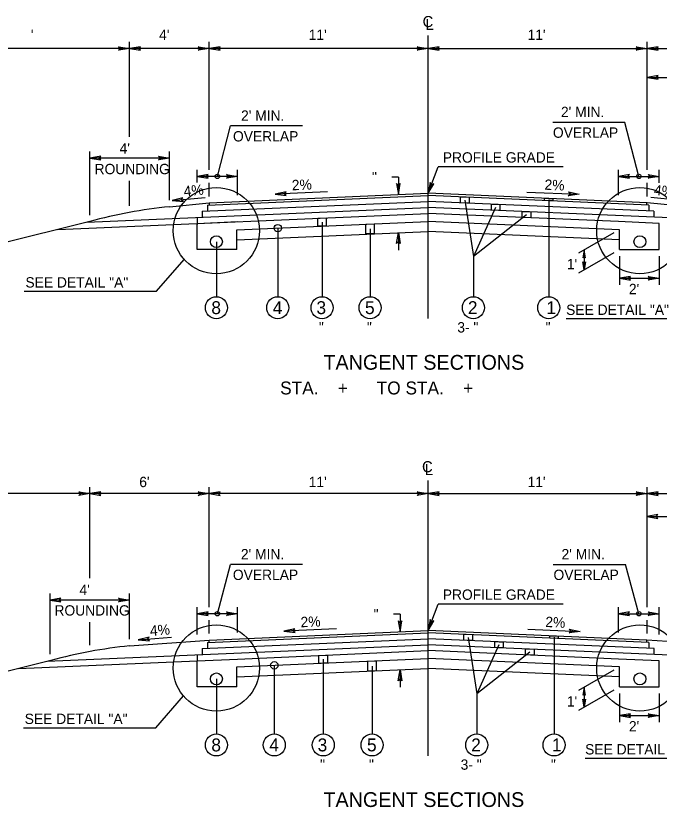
# Model space of a CAD drawing. Extents: x -540 to 1231, y -564 to 421.
# Drawn here: x -54.4 to 32.7, y 179.1 to 286.3 of the extents above; entities that cross this region are included whole.
import ezdxf

# ---------------------------------------------------------------- set-up
doc = ezdxf.new("R2010")
doc.units = 0
doc.layers.add('1', color=7, linetype='Continuous')
doc.layers.add('Des_ Drain_ Ftrs', color=7, linetype='Continuous')

msp = doc.modelspace()

# ---------------------------------------------------------------- linework, layer by layer
at = {"layer": '1'}
for p, q in [((1.43, 245.31), (1.43, 283.66)), ((-38.98, 281.9), (-64.39, 281.9)), ((-38.98, 269.95), (-38.98, 282.78)), ((-28.2, 281.9), (-38.98, 281.9)), ((-28.2, 265.45), (-28.2, 282.78)), ((1.43, 281.9), (-28.2, 281.9)), ((1.43, 281.9), (31.07, 281.9)), ((31.07, 265.45), (31.07, 282.78)), ((31.07, 281.9), (41.85, 281.9)), ((31.09, 277.97), (48.06, 277.97)), ((-27.1, 264.57), (-25.31, 271.4)), ((-15.55, 271.4), (-25.31, 271.4)), ((18.3, 271.9), (28.06, 271.9)), ((29.97, 264.57), (28.08, 271.85)), ((-44.37, 259.34), (-44.37, 267.93)), ((-33.59, 267.05), (-44.37, 267.05)), ((-33.59, 261.35), (-33.59, 267.93)), ((1.43, 262.29), (2.81, 265.86)), ((19.73, 265.86), (2.81, 265.86)), ((-29.84, 263.75), (-29.84, 265.45)), ((-24.36, 262.04), (-24.36, 265.45)), ((27.23, 262.04), (27.23, 265.45)), ((32.71, 263.69), (32.71, 265.45)), ((-38.98, 260.57), (-38.98, 263.98)), ((-24.36, 264.57), (-29.84, 264.57)), ((-28.2, 261.87), (-28.2, 263.69)), ((-2.59, 264.48), (-3.47, 264.48)), ((-2.59, 264.48), (-2.59, 262.11)), ((27.23, 264.57), (32.71, 264.57)), ((31.07, 261.87), (31.07, 263.69)), ((-33.21, 261.3), (-28.73, 261.73)), ((-28.44, 260.68), (1.43, 261.99)), ((-28.21, 260.99), (1.43, 262.29)), ((-12.17, 262.47), (-19.26, 262.16)), ((31.07, 260.99), (1.43, 262.29)), ((31.31, 260.68), (1.43, 261.99)), ((14.81, 262.45), (21.9, 262.15)), ((36.05, 261.26), (31.57, 261.7)), ((-33.59, 260.47), (-28.21, 260.99)), ((-29.14, 259.84), (1.43, 261.18)), ((-28.44, 260.68), (-28.44, 259.88)), ((-28.21, 260.99), (-28.21, 260.69)), ((32.01, 259.84), (1.43, 261.18)), ((6.4, 261.37), (7.57, 253.74)), ((17.76, 261.41), (17.76, 248.28)), ((31.06, 260.69), (31.06, 261)), ((36.46, 260.47), (31.07, 260.99)), ((31.31, 260.68), (31.31, 259.88)), ((-48.71, 257.37), (1.43, 259.56)), ((-44.79, 258.35), (1.43, 260.37)), ((-29.14, 259.84), (-29.14, 259.04)), ((47.65, 258.35), (1.43, 260.37)), ((27.23, 258.44), (1.43, 259.56)), ((10.58, 260.38), (7.57, 253.74)), ((14.75, 259.37), (7.57, 253.74)), ((32.01, 259.84), (32.01, 259.04)), ((-44.37, 258.46), (-64.39, 253.45)), ((-29.85, 259), (-29.85, 258.05)), ((-29.85, 258.2), (-24.36, 258.44)), ((-24.46, 257.35), (1.43, 258.48)), ((-12.92, 258.39), (-12.92, 248.28)), ((27.33, 257.35), (1.43, 258.48)), ((32.72, 258.2), (27.23, 258.44)), ((-29.85, 254.66), (-29.85, 258.2)), ((-24.46, 254.66), (-24.46, 257.35)), ((-18.92, 257.57), (-18.92, 248.28)), ((-6.42, 257.47), (-6.42, 248.28)), ((27.33, 254.66), (27.33, 257.35)), ((27.33, 257.35), (27.33, 257.35)), ((32.72, 254.66), (32.72, 258.2)), ((-24.46, 256), (1.43, 257.13)), ((-2.59, 256.96), (-2.59, 254.59)), ((27.33, 256), (1.43, 257.13)), ((26.57, 256.91), (21.81, 254.17)), ((-27.23, 255.73), (-27.23, 248.28)), ((-24.46, 254.66), (-29.85, 254.66)), ((26.57, 254.22), (21.79, 251.46)), ((22.57, 254.61), (22.55, 251.9)), ((27.33, 254.66), (32.72, 254.66)), ((-35.34, 249.01), (-31.6, 253.33)), ((7.57, 253.74), (7.57, 248.28)), ((27.33, 253.78), (27.33, 249.89)), ((32.72, 253.78), (32.72, 249.89)), ((27.33, 250.77), (32.72, 250.77)), ((-53.27, 249.01), (-35.34, 249.01)), ((20.11, 245.31), (38.9, 245.31)), ((1.43, 186.09), (1.43, 223.37)), ((-44.37, 210.17), (-44.37, 222.49)), ((-28.2, 206.22), (-28.2, 222.49)), ((31.07, 206.22), (31.07, 222.49)), ((-44.37, 221.61), (-69.73, 221.61)), ((-28.2, 221.61), (-44.37, 221.61)), ((1.43, 221.61), (-28.2, 221.61)), ((1.43, 221.61), (31.07, 221.61)), ((31.07, 221.61), (47.23, 221.61)), ((31.06, 218.51), (53.42, 218.51)), ((-27.1, 205.34), (-25.34, 212.01)), ((-15.57, 212.01), (-25.34, 212.01)), ((18.38, 212.01), (28.14, 212.01)), ((29.97, 205.34), (28.14, 212.01)), ((-49.75, 199.87), (-49.75, 208.07)), ((-38.98, 201.88), (-38.98, 208.07)), ((-38.98, 207.19), (-49.75, 207.19)), ((-29.84, 202.53), (-29.84, 206.22)), ((-24.36, 202.82), (-24.36, 206.22)), ((1.43, 203.07), (2.81, 206.64)), ((19.73, 206.64), (2.81, 206.64)), ((27.23, 202.82), (27.23, 206.22)), ((32.71, 202.54), (32.71, 206.22)), ((-24.36, 205.34), (-29.84, 205.34)), ((-2.36, 205.27), (-3.24, 205.27)), ((-2.36, 205.27), (-2.36, 202.9)), ((27.23, 205.34), (32.71, 205.34)), ((-44.37, 201.1), (-44.37, 204.21)), ((-28.2, 202.65), (-28.2, 204.46)), ((31.07, 202.65), (31.07, 204.46)), ((-28.44, 201.46), (1.43, 202.77)), ((-28.21, 201.77), (1.43, 203.07)), ((-10.99, 203.3), (-18.08, 202.99)), ((31.06, 201.77), (1.43, 203.07)), ((31.31, 201.46), (1.43, 202.77)), ((14.92, 203.23), (22.01, 202.92)), ((-38.98, 201), (-28.21, 201.77)), ((-37.8, 201.82), (-33.32, 202.15)), ((-29.15, 200.62), (1.43, 201.96)), ((-28.21, 201.47), (-28.21, 201.77)), ((32.02, 200.62), (1.43, 201.96)), ((6.86, 202.12), (8.02, 194.5)), ((18.49, 202.16), (18.49, 189.06)), ((41.85, 201), (31.06, 201.77)), ((31.06, 201.47), (31.06, 201.77)), ((-50.12, 198.9), (1.43, 201.15)), ((-29.15, 200.62), (-29.15, 199.81)), ((-28.44, 201.46), (-28.44, 200.65)), ((52.98, 198.9), (1.43, 201.15)), ((11.03, 201.14), (8.02, 194.5)), ((31.31, 201.46), (31.31, 200.65)), ((32.01, 200.62), (32.01, 199.82)), ((-29.85, 199.78), (-29.85, 198.97)), ((-24.36, 199.21), (1.43, 200.34)), ((27.23, 199.21), (1.43, 200.34)), ((15.21, 200.13), (8.02, 194.5)), ((-49.63, 199.02), (-69.73, 194)), ((-54.04, 197.92), (-29.85, 198.97)), ((-29.85, 198.97), (-24.36, 199.21)), ((-29.85, 195.44), (-29.85, 198.97)), ((-24.46, 198.13), (1.43, 199.26)), ((-19.39, 198.35), (-19.39, 189.06)), ((-12.76, 199.18), (-12.76, 189.06)), ((27.33, 198.13), (1.43, 199.26)), ((32.72, 198.97), (27.23, 199.21)), ((32.72, 195.44), (32.72, 198.97)), ((-24.46, 195.44), (-24.46, 198.13)), ((-24.46, 196.78), (1.43, 197.91)), ((-6.15, 198.26), (-6.15, 189.06)), ((-2.36, 197.75), (-2.36, 195.38)), ((27.33, 196.78), (1.43, 197.91)), ((26.57, 197.69), (21.81, 194.94)), ((27.33, 195.44), (27.33, 198.13)), ((27.33, 198.13), (27.33, 198.13)), ((-27.23, 196.51), (-27.23, 189.06)), ((-24.46, 195.44), (-29.85, 195.44)), ((22.57, 195.38), (22.55, 192.68)), ((27.33, 195.44), (32.72, 195.44)), ((-35.43, 189.9), (-31.69, 194.22)), ((8.02, 194.5), (8.02, 189.06)), ((26.57, 195), (21.79, 192.24)), ((27.33, 194.56), (27.33, 190.67)), ((32.72, 194.56), (32.72, 190.67)), ((27.33, 191.55), (32.72, 191.55)), ((-53.36, 189.9), (-35.43, 189.9)), ((22.68, 185.78), (41.47, 185.78))]:
    msp.add_line(p, q, dxfattribs=at)
for points in [[(5.83, 261.8), (6.98, 261.75), (6.98, 260.94), (5.83, 260.99)], [(17.19, 261.6), (18.34, 261.55), (18.34, 261.25), (17.19, 261.3)], [(10.01, 260.81), (11.15, 260.76), (11.15, 259.95), (10.01, 260)], [(14.18, 259.81), (15.33, 259.76), (15.33, 258.95), (14.18, 259)], [(-13.5, 258.91), (-12.35, 258.96), (-12.35, 257.88), (-13.5, 257.83)], [(-7, 258.11), (-5.85, 258.16), (-5.85, 256.82), (-7, 256.77)], [(6.28, 202.56), (7.43, 202.51), (7.43, 201.7), (6.28, 201.75)], [(10.46, 201.56), (11.6, 201.51), (11.6, 200.71), (10.46, 200.76)], [(17.91, 202.35), (19.06, 202.3), (19.06, 202), (17.91, 202.05)], [(14.63, 200.57), (15.78, 200.52), (15.78, 199.71), (14.63, 199.76)], [(-13.34, 199.7), (-12.19, 199.75), (-12.19, 198.67), (-13.34, 198.62)], [(-6.72, 198.91), (-5.58, 198.96), (-5.58, 197.61), (-6.72, 197.56)]]:
    msp.add_lwpolyline(points, close=True, dxfattribs=at)
for centre, radius in [((-27.1, 264.57), 0.3), ((29.97, 264.57), 0.3), ((-27.24, 257.22), 5.84), ((30.1, 257.22), 5.84), ((-18.92, 257.57), 0.5), ((-27.23, 255.73), 0.808), ((30.1, 255.73), 0.808), ((-27.23, 246.79), 1.49), ((-18.92, 246.79), 1.49), ((-12.92, 246.79), 1.49), ((-6.42, 246.79), 1.49), ((7.57, 246.79), 1.49), ((17.76, 246.79), 1.49), ((-27.1, 205.34), 0.3), ((29.97, 205.34), 0.3), ((-27.24, 197.99), 5.84), ((30.1, 197.99), 5.84), ((-19.39, 198.35), 0.5), ((-27.23, 196.51), 0.808), ((30.1, 196.51), 0.808), ((-27.23, 187.57), 1.49), ((-19.39, 187.57), 1.49), ((-12.76, 187.57), 1.49), ((-6.15, 187.57), 1.49), ((8.02, 187.57), 1.49), ((18.49, 187.57), 1.49)]:
    msp.add_circle(centre, radius, dxfattribs=at)
for centre, end in [((-26.71, 193.63), 105.2381), ((-32.09, 134.16), 105.1262)]:
    msp.add_arc(centre, 67.19, 95.8795, end, dxfattribs=at)
at = {"layer": 'Des_ Drain_ Ftrs'}
for points in [[(-38.98, 281.9), (-40.47, 281.65), (-40.17, 281.9), (-40.47, 282.14)], [(-38.98, 281.9), (-37.49, 281.65), (-37.78, 281.9), (-37.49, 282.14)], [(-28.2, 281.9), (-29.69, 281.65), (-29.39, 281.9), (-29.69, 282.14)], [(-28.2, 281.9), (-26.71, 281.65), (-27.01, 281.9), (-26.71, 282.14)], [(1.43, 281.9), (-0.05, 281.65), (0.24, 281.9), (-0.05, 282.14)], [(1.43, 281.9), (2.92, 281.65), (2.63, 281.9), (2.92, 282.14)], [(31.07, 281.9), (29.58, 281.65), (29.88, 281.9), (29.58, 282.14)], [(31.07, 281.9), (32.56, 281.65), (32.26, 281.9), (32.56, 282.14)], [(31.09, 277.97), (32.58, 277.72), (32.28, 277.97), (32.58, 278.22)], [(-44.37, 267.05), (-42.88, 266.81), (-43.17, 267.05), (-42.88, 267.3)], [(-33.59, 267.05), (-35.08, 266.81), (-34.78, 267.05), (-35.08, 267.3)], [(-29.84, 264.57), (-28.35, 264.32), (-28.65, 264.57), (-28.35, 264.82)], [(-24.36, 264.57), (-25.85, 264.32), (-25.55, 264.57), (-25.85, 264.82)], [(27.23, 264.57), (28.71, 264.32), (28.42, 264.57), (28.71, 264.82)], [(32.71, 264.57), (31.22, 264.32), (31.52, 264.57), (31.22, 264.82)], [(1.43, 262.28), (2.2, 263.58), (1.86, 263.4), (1.73, 263.76)], [(-2.59, 262.11), (-2.34, 263.6), (-2.59, 263.3), (-2.84, 263.6)], [(-33.21, 261.3), (-31.7, 261.19), (-32.02, 261.41), (-31.75, 261.69)], [(-19.26, 262.16), (-17.76, 261.98), (-18.07, 262.21), (-17.78, 262.48)], [(21.9, 262.15), (20.4, 261.96), (20.7, 262.2), (20.42, 262.46)], [(-2.59, 256.96), (-2.34, 255.47), (-2.59, 255.77), (-2.84, 255.47)], [(22.57, 254.61), (22.38, 253.52), (22.56, 253.74), (22.74, 253.52)], [(22.55, 251.9), (22.38, 252.98), (22.56, 252.77), (22.74, 252.98)], [(27.33, 250.77), (28.82, 250.52), (28.52, 250.77), (28.82, 251.02)], [(32.72, 250.77), (31.23, 250.52), (31.52, 250.77), (31.23, 251.02)], [(-44.37, 221.61), (-45.85, 221.36), (-45.56, 221.61), (-45.85, 221.86)], [(-44.37, 221.61), (-42.88, 221.36), (-43.17, 221.61), (-42.88, 221.86)], [(-28.2, 221.61), (-29.69, 221.36), (-29.39, 221.61), (-29.69, 221.86)], [(-28.2, 221.61), (-26.71, 221.36), (-27.01, 221.61), (-26.71, 221.86)], [(1.43, 221.61), (-0.05, 221.36), (0.24, 221.61), (-0.05, 221.86)], [(1.43, 221.61), (2.92, 221.36), (2.63, 221.61), (2.92, 221.86)], [(31.07, 221.61), (29.58, 221.36), (29.88, 221.61), (29.58, 221.86)], [(31.07, 221.61), (32.56, 221.36), (32.26, 221.61), (32.56, 221.86)], [(31.06, 218.51), (32.55, 218.26), (32.25, 218.51), (32.55, 218.76)], [(-49.75, 207.19), (-48.27, 206.94), (-48.56, 207.19), (-48.27, 207.44)], [(-38.98, 207.19), (-40.47, 206.94), (-40.17, 207.19), (-40.47, 207.44)], [(-29.84, 205.34), (-28.35, 205.09), (-28.65, 205.34), (-28.35, 205.59)], [(-24.36, 205.34), (-25.85, 205.09), (-25.55, 205.34), (-25.85, 205.59)], [(27.23, 205.34), (28.71, 205.09), (28.42, 205.34), (28.71, 205.59)], [(32.71, 205.34), (31.22, 205.09), (31.52, 205.34), (31.22, 205.59)], [(-2.36, 202.9), (-2.12, 204.39), (-2.36, 204.1), (-2.61, 204.39)], [(1.43, 203.07), (2.2, 204.37), (1.86, 204.18), (1.73, 204.55)], [(-18.08, 202.99), (-16.58, 202.8), (-16.89, 203.04), (-16.6, 203.3)], [(22.01, 202.92), (20.51, 202.74), (20.82, 202.97), (20.53, 203.24)], [(-37.8, 201.82), (-36.3, 201.68), (-36.61, 201.91), (-36.34, 202.18)], [(-2.36, 197.75), (-2.12, 196.26), (-2.36, 196.56), (-2.61, 196.26)], [(22.57, 195.38), (22.38, 194.3), (22.56, 194.51), (22.74, 194.3)], [(22.55, 192.68), (22.38, 193.76), (22.56, 193.55), (22.74, 193.76)], [(27.33, 191.55), (28.82, 191.3), (28.52, 191.55), (28.82, 191.8)], [(32.72, 191.55), (31.23, 191.3), (31.52, 191.55), (31.23, 191.8)]]:
    msp.add_lwpolyline(points, close=True, dxfattribs=at)

# ---------------------------------------------------------------- texts
at = {"layer": '1'}
for s, height, p in [("  '", 1.4, (-53.38, 283.05)), ("4'", 1.4, (-34.98, 283.05)), ("11'", 1.4, (-14.73, 283.05)), ("11'", 1.4, (14.9, 283.05)), ("2' MIN.", 1.4, (-23.89, 272.1)), ("2' MIN.", 1.4, (19.42, 272.6)), ('OVERLAP', 1.4, (18.33, 269.8)), ('OVERLAP', 1.4, (-24.98, 269.3)), ("4'", 1.4, (-40.33, 267.67)), ('PROFILE GRADE', 1.4, (3.42, 266.44)), ('ROUNDING', 1.4, (-43.72, 264.87)), ('SEE DETAIL "A"', 1.4, (-53.08, 249.52)), ("2'", 1.4, (28.62, 248.62)), ('8', 1.75, (-27.91, 245.92)), ('4', 1.75, (-19.59, 245.92)), ('3', 1.75, (-13.68, 245.92)), ('5', 1.75, (-7.11, 245.92)), ('2', 1.75, (6.82, 245.92)), ('1', 1.75, (17.46, 245.92)), ('SEE DETAIL "A"', 1.4, (20.12, 245.81)), (' "', 1.4, (-13.87, 243.43)), (' "', 1.4, (-7.37, 243.43)), ('3- "', 1.4, (5.39, 243.43)), (' "', 1.4, (16.82, 243.43)), ('TANGENT SECTIONS', 2, (-12.74, 238.39)), ('STA.    +      TO STA.    +     ', 1.75, (-18.6, 235.04)), ("6'", 1.4, (-37.67, 222.49)), ("11'", 1.4, (-14.73, 222.49)), ("11'", 1.4, (14.9, 222.49)), ("2' MIN.", 1.4, (-23.91, 212.71)), ("2' MIN.", 1.4, (19.5, 212.71)), ('OVERLAP', 1.4, (-25, 209.91)), ('OVERLAP', 1.4, (18.41, 209.91)), ("4'", 1.4, (-45.76, 207.89)), ('PROFILE GRADE', 1.4, (3.42, 207.23)), ('ROUNDING', 1.4, (-49.15, 205.09)), ('SEE DETAIL "A"', 1.4, (-53.18, 190.41)), ("2'", 1.4, (28.62, 189.4)), ('8', 1.75, (-27.91, 186.7)), ('4', 1.75, (-20.07, 186.7)), ('3', 1.75, (-13.52, 186.7)), ('5', 1.75, (-6.84, 186.7)), ('2', 1.75, (7.27, 186.7)), ('1', 1.75, (18.19, 186.7)), ('SEE DETAIL "A"', 1.4, (22.69, 186.28)), (' "', 1.4, (-13.71, 184.21)), (' "', 1.4, (-7.09, 184.21)), ('3- "', 1.4, (5.84, 184.21)), (' "', 1.4, (17.54, 184.21)), ('TANGENT SECTIONS', 2, (-12.74, 179.17))]:
    msp.add_text(s, height=height, dxfattribs=at).set_placement(p)
for s, rotation, p in [('  "', 0.1438, (-7.2, 263.78)), ('2%', 2.6235, (-16.98, 262.68)), ('2%', 357.3765, (17.17, 262.77)), ('4%', 5.86, (-31.59, 261.84)), ('4%', 354.1268, (31.95, 262.06)), ("1'", 0.1438, (20.22, 251.99)), ('  "', 0.1438, (-6.98, 204.57)), ('2%', 2.6262, (-15.8, 203.5)), ('2%', 357.376, (17.28, 203.55)), ('4%', 4.4031, (-36.17, 202.33)), ("1'", 0.1438, (20.22, 192.77))]:
    msp.add_text(s, height=1.4, rotation=rotation, dxfattribs=at).set_placement(p)
at = {"layer": 'Des_ Drain_ Ftrs'}
for s, p in [('C', (0.69, 284.79)), ('L', (1.09, 284.4)), ('C', (0.61, 224.5)), ('L', (1, 224.11))]:
    msp.add_text(s, height=1.5, dxfattribs=at).set_placement(p)

doc.saveas('drawing.dxf')
